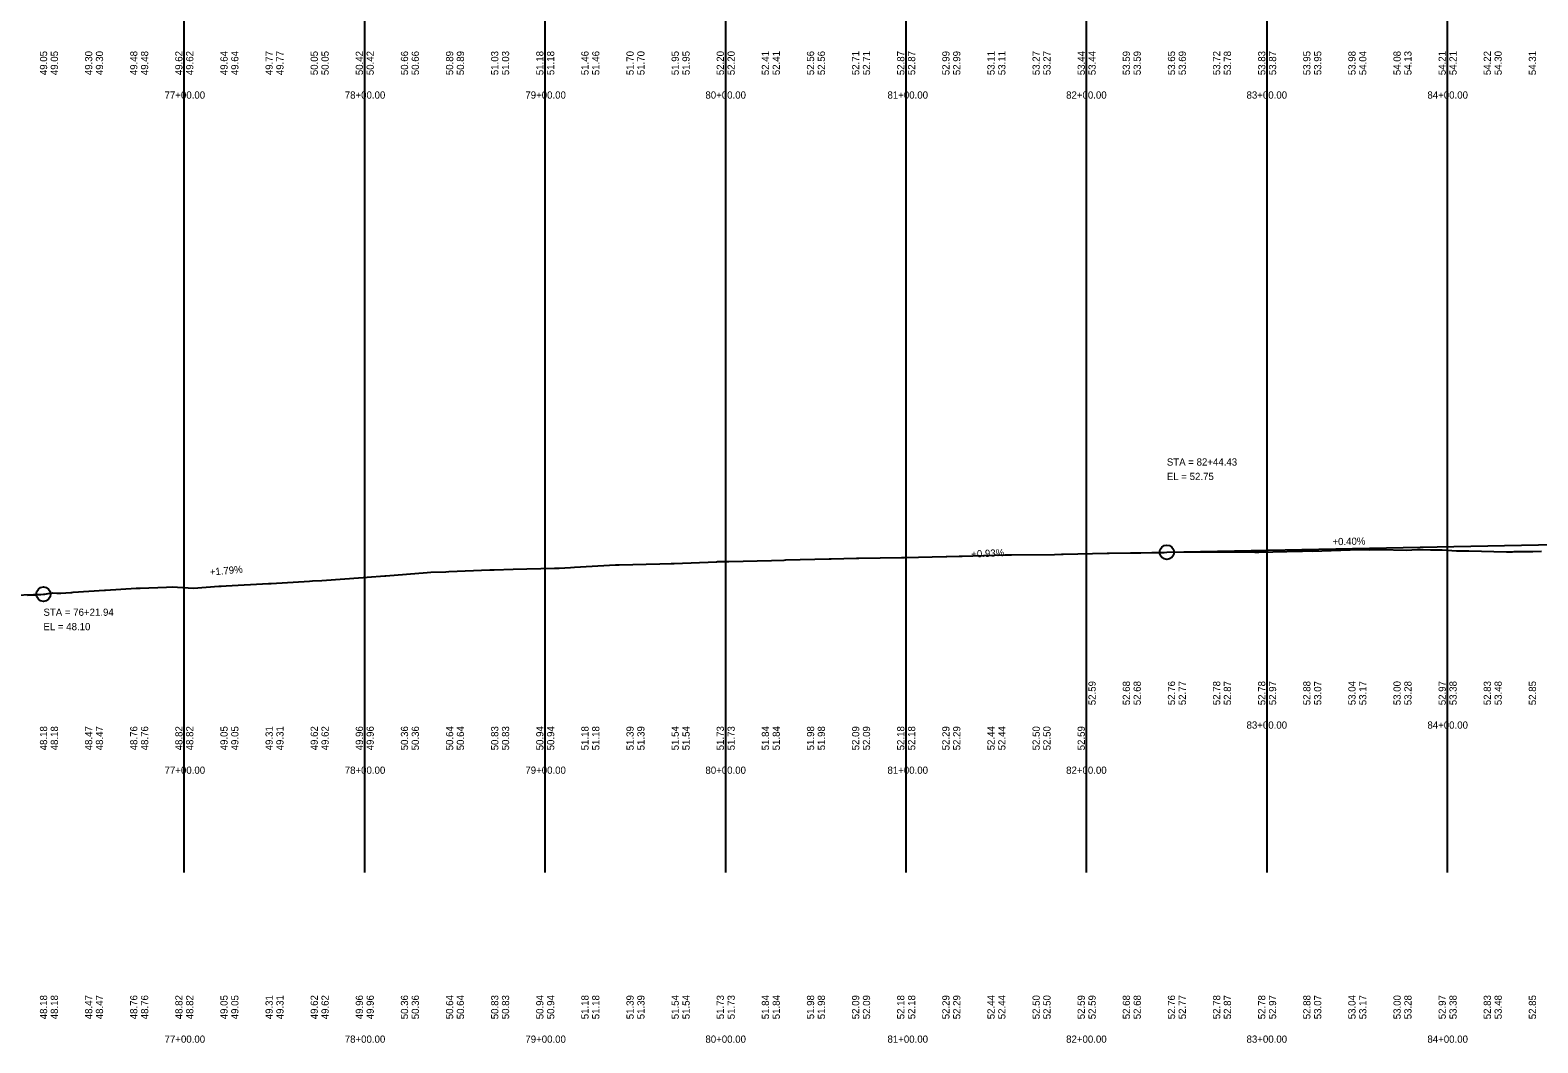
# Model space of a CAD drawing. Extents: x 3880794 to 3915434, y 287517 to 300173.
# Drawn here: x 3906766 to 3907601, y 292382 to 292943 of the extents above; entities that cross this region are included whole.
import ezdxf

# ---------------------------------------------------------------- set-up
doc = ezdxf.new("R2010")
doc.units = 0
for name, color, linetype in [('Level 1', 7, 'Continuous'), ('Level 30', 7, 'Continuous'), ('Level 31', 7, 'Continuous'), ('Level 32', 7, 'Continuous')]:
    doc.layers.add(name, color=color, linetype=linetype)

msp = doc.modelspace()

# ---------------------------------------------------------------- linework, layer by layer
at = {"layer": 'Level 1'}
for p, q in [((3906851.21, 292476.49), (3906851.21, 293504.13)), ((3906951.21, 292476.49), (3906951.21, 293504.13)), ((3907051.21, 292476.49), (3907051.21, 293504.13)), ((3907151.21, 292476.49), (3907151.21, 293504.13)), ((3907251.21, 292476.49), (3907251.21, 293504.13)), ((3907351.21, 292476.49), (3907351.21, 293504.13)), ((3907451.21, 292476.49), (3907451.21, 293504.13)), ((3907551.21, 292476.49), (3907551.21, 293504.13)), ((3907395.64, 292653.84), (3907801.21, 292662.05)), ((3907067.42, 292645.49), (3907090.19, 292646.8)), ((3907090.19, 292646.8), (3907092.19, 292646.83)), ((3907092.19, 292646.83), (3907114.74, 292647.4)), ((3907114.74, 292647.4), (3907121.01, 292647.65)), ((3907121.01, 292647.65), (3907122.73, 292647.69)), ((3907122.73, 292647.69), (3907146.06, 292648.61)), ((3907146.06, 292648.61), (3907146.59, 292648.63)), ((3907146.59, 292648.63), (3907151.39, 292648.74)), ((3907151.39, 292648.74), (3907152.85, 292648.78)), ((3907152.85, 292648.78), (3907176.59, 292649.33)), ((3907176.59, 292649.33), (3907183.63, 292649.52)), ((3907183.63, 292649.52), (3907184.47, 292649.57)), ((3907184.47, 292649.57), (3907208.55, 292650.23)), ((3907208.55, 292650.23), (3907209.61, 292650.26)), ((3907209.61, 292650.26), (3907223.66, 292650.52)), ((3907223.66, 292650.52), (3907224.89, 292650.52)), ((3907224.89, 292650.52), (3907248.61, 292650.95)), ((3907248.61, 292650.95), (3907250.21, 292650.98)), ((3907250.21, 292650.98), (3907273.4, 292651.5)), ((3907273.4, 292651.5), (3907273.78, 292651.5)), ((3907273.78, 292651.5), (3907280.62, 292651.72)), ((3907280.62, 292651.72), (3907282.24, 292651.73)), ((3907282.24, 292651.73), (3907305.82, 292652.46)), ((3907305.82, 292652.46), (3907308.15, 292652.48)), ((3907308.15, 292652.48), (3907309.6, 292652.48)), ((3907309.6, 292652.48), (3907333.33, 292652.65)), ((3907333.33, 292652.65), (3907337.24, 292652.74)), ((3907337.24, 292652.74), (3907338.1, 292652.75)), ((3907338.1, 292652.75), (3907362.58, 292653.3)), ((3907362.58, 292653.3), (3907363.69, 292653.32)), ((3907363.69, 292653.32), (3907381.16, 292653.61)), ((3907381.16, 292653.61), (3907387.37, 292653.71)), ((3907387.37, 292653.71), (3907394.16, 292653.78)), ((3907394.16, 292653.78), (3907395.64, 292653.84)), ((3906899.38, 292636.52), (3906920.66, 292637.82)), ((3906920.66, 292637.82), (3906922.29, 292637.93)), ((3906922.29, 292637.93), (3906927.38, 292638.28)), ((3906927.38, 292638.28), (3906950.25, 292639.84)), ((3906950.25, 292639.84), (3906952.49, 292639.99)), ((3906952.49, 292639.99), (3906962.36, 292640.8)), ((3906962.36, 292640.8), (3906962.95, 292640.84)), ((3906962.95, 292640.84), (3906985.76, 292642.71)), ((3906985.76, 292642.71), (3906987.83, 292642.74)), ((3906987.83, 292642.74), (3906996.2, 292643.05)), ((3906996.2, 292643.05), (3906997.87, 292643.2)), ((3906997.87, 292643.2), (3907020.51, 292644.04)), ((3907020.51, 292644.04), (3907022.96, 292644.16)), ((3907022.96, 292644.16), (3907033.5, 292644.42)), ((3907033.5, 292644.42), (3907056.26, 292644.95)), ((3907056.26, 292644.95), (3907058.49, 292645)), ((3907058.49, 292645), (3907058.95, 292645.01)), ((3907058.95, 292645.01), (3907065.29, 292645.37)), ((3907065.29, 292645.37), (3907067.42, 292645.49)), ((3906751.21, 292629.89), (3906773.16, 292630.63)), ((3906773.16, 292630.63), (3906773.94, 292630.7)), ((3906773.94, 292630.7), (3906775.7, 292630.94)), ((3906775.7, 292630.94), (3906778.36, 292631.31)), ((3906778.36, 292631.31), (3906780.63, 292631.2)), ((3906780.63, 292631.2), (3906781.31, 292631.23)), ((3906781.31, 292631.23), (3906782.49, 292631.2)), ((3906782.49, 292631.2), (3906782.79, 292631.21)), ((3906782.79, 292631.21), (3906788.4, 292631.52)), ((3906788.4, 292631.52), (3906788.85, 292631.58)), ((3906788.85, 292631.58), (3906789.61, 292631.64)), ((3906789.61, 292631.64), (3906806.96, 292632.87)), ((3906806.96, 292632.87), (3906807.59, 292632.81)), ((3906807.59, 292632.81), (3906824.54, 292633.89)), ((3906824.54, 292633.89), (3906826.69, 292633.89)), ((3906826.69, 292633.89), (3906841.38, 292634.5)), ((3906841.38, 292634.5), (3906844.48, 292634.63)), ((3906844.48, 292634.63), (3906856.38, 292633.92)), ((3906856.38, 292633.92), (3906870.32, 292635.04)), ((3906870.32, 292635.04), (3906871.6, 292635.11)), ((3906871.6, 292635.11), (3906874.42, 292635.25)), ((3906874.42, 292635.25), (3906897.89, 292636.48)), ((3906897.89, 292636.48), (3906899.38, 292636.52))]:
    msp.add_line(p, q, dxfattribs=at)
for points in [[(3906826.69, 292633.89), (3906841.38, 292634.5), (3906844.48, 292634.63), (3906856.38, 292633.92), (3906870.32, 292635.04), (3906871.6, 292635.11), (3906874.42, 292635.25), (3906897.89, 292636.48), (3906899.38, 292636.52), (3906920.66, 292637.82), (3906922.29, 292637.93), (3906927.38, 292638.28), (3906950.25, 292639.84), (3906952.49, 292639.99), (3906962.36, 292640.8), (3906962.95, 292640.84), (3906985.76, 292642.71), (3906987.83, 292642.74), (3906996.2, 292643.05), (3906997.87, 292643.2), (3907020.51, 292644.04), (3907022.96, 292644.16), (3907033.5, 292644.42), (3907056.26, 292644.95), (3907058.49, 292645), (3907058.95, 292645.01), (3907065.29, 292645.37), (3907067.42, 292645.49), (3907090.19, 292646.8), (3907092.19, 292646.83), (3907114.74, 292647.4), (3907121.01, 292647.65), (3907122.73, 292647.69), (3907146.06, 292648.61), (3907146.59, 292648.63), (3907151.39, 292648.74), (3907152.85, 292648.78), (3907176.59, 292649.33), (3907183.63, 292649.52), (3907184.47, 292649.57), (3907208.55, 292650.23), (3907209.61, 292650.26), (3907223.66, 292650.52), (3907224.89, 292650.52), (3907248.61, 292650.95), (3907250.21, 292650.98), (3907273.4, 292651.5), (3907273.78, 292651.5), (3907280.62, 292651.72), (3907282.24, 292651.73), (3907305.82, 292652.46), (3907308.15, 292652.48), (3907309.6, 292652.48), (3907333.33, 292652.65), (3907337.24, 292652.74), (3907338.1, 292652.75), (3907362.58, 292653.3), (3907363.69, 292653.32), (3907387.37, 292653.71), (3907394.16, 292653.78), (3907395.64, 292653.84), (3907419.16, 292654.07), (3907420.61, 292654.06), (3907444.32, 292653.87), (3907444.91, 292653.93), (3907445.77, 292653.95), (3907446.65, 292653.93), (3907469.81, 292654.43), (3907470.79, 292654.45), (3907473.08, 292654.54), (3907474.38, 292654.54), (3907476.27, 292654.5), (3907497.22, 292655.22), (3907500.5, 292655.31), (3907507.88, 292655.18), (3907514.07, 292655.29), (3907528.22, 292655.07), (3907534.61, 292655.4), (3907536.39, 292655.33), (3907537.62, 292655.35), (3907541.66, 292655.2), (3907545.06, 292655.12), (3907548.27, 292655.11), (3907556.2, 292654.71), (3907560.34, 292654.64), (3907563.01, 292654.57), (3907583.86, 292654.07), (3907587.12, 292654.02), (3907588.09, 292654.34), (3907591.56, 292654.3), (3907598.36, 292654.31), (3907603.21, 292654.42)], [(3906764.32, 292629.98), (3906768.41, 292630.17), (3906769.43, 292630.29), (3906773.94, 292630.7), (3906775.7, 292630.94), (3906778.36, 292631.31), (3906780.63, 292631.2), (3906781.31, 292631.23), (3906782.49, 292631.2), (3906782.79, 292631.21), (3906788.4, 292631.52), (3906788.85, 292631.58), (3906789.61, 292631.64), (3906806.96, 292632.87), (3906807.59, 292632.81), (3906824.54, 292633.89), (3906826.69, 292633.89)]]:
    msp.add_lwpolyline(points, dxfattribs=at)
for centre in [(3907395.64, 292653.84), (3906773.16, 292630.63)]:
    msp.add_circle(centre, 4, dxfattribs=at)

# ---------------------------------------------------------------- texts
at = {"layer": 'Level 30'}
for s, p in [('77+00.00', (3906840.29, 292905.16)), ('77+00.00', (3906840.29, 292905.16)), ('78+00.00', (3906940.13, 292905.16)), ('78+00.00', (3906940.13, 292905.16)), ('79+00.00', (3907040.19, 292905.16)), ('79+00.00', (3907040.19, 292905.16)), ('80+00.00', (3907139.97, 292905.16)), ('80+00.00', (3907139.97, 292905.16)), ('81+00.00', (3907240.85, 292905.16)), ('81+00.00', (3907240.85, 292905.16)), ('82+00.00', (3907339.84, 292905.16)), ('82+00.00', (3907339.84, 292905.16)), ('83+00.00', (3907439.81, 292905.16)), ('83+00.00', (3907439.81, 292905.16)), ('84+00.00', (3907540.03, 292905.16)), ('84+00.00', (3907540.03, 292905.16)), ('83+00.00', (3907439.81, 292556.11)), ('83+00.00', (3907439.81, 292556.11)), ('84+00.00', (3907540.03, 292556.11)), ('84+00.00', (3907540.03, 292556.11)), ('77+00.00', (3906840.29, 292531.11)), ('77+00.00', (3906840.29, 292531.11)), ('78+00.00', (3906940.13, 292531.11)), ('78+00.00', (3906940.13, 292531.11)), ('79+00.00', (3907040.19, 292531.11)), ('79+00.00', (3907040.19, 292531.11)), ('80+00.00', (3907139.97, 292531.11)), ('80+00.00', (3907139.97, 292531.11)), ('81+00.00', (3907240.85, 292531.11)), ('81+00.00', (3907240.85, 292531.11)), ('82+00.00', (3907339.84, 292531.11)), ('82+00.00', (3907339.84, 292531.11)), ('77+00.00', (3906840.29, 292382.11)), ('77+00.00', (3906840.29, 292382.11)), ('78+00.00', (3906940.13, 292382.11)), ('78+00.00', (3906940.13, 292382.11)), ('79+00.00', (3907040.19, 292382.11)), ('79+00.00', (3907040.19, 292382.11)), ('80+00.00', (3907139.97, 292382.11)), ('80+00.00', (3907139.97, 292382.11)), ('81+00.00', (3907240.85, 292382.11)), ('81+00.00', (3907240.85, 292382.11)), ('82+00.00', (3907339.84, 292382.11)), ('82+00.00', (3907339.84, 292382.11)), ('83+00.00', (3907439.81, 292382.11)), ('83+00.00', (3907439.81, 292382.11)), ('84+00.00', (3907540.03, 292382.11)), ('84+00.00', (3907540.03, 292382.11))]:
    msp.add_text(s, height=4, dxfattribs=at).set_placement(p)
at = {"layer": 'Level 31'}
for s, p in [('STA = 82+44.43', (3907395.64, 292701.85)), ('EL = 52.75', (3907395.64, 292693.85)), ('STA = 76+21.94', (3906773.16, 292618.63)), ('EL = 48.10', (3906773.16, 292610.63))]:
    msp.add_text(s, height=4, dxfattribs=at).set_placement(p)
for s, rotation, p in [('+0.93%', 2.66002, (3907287.35, 292650.82)), ('+0.40%', 1.15914, (3907487.42, 292657.7)), ('+1.79%', 5.11098, (3906865.49, 292640.9)), ('52.59', 90, (3907356.21, 292569.11)), ('52.68', 90, (3907375.21, 292569.11)), ('52.68', 90, (3907381.21, 292569.11)), ('52.76', 90, (3907400.21, 292569.11)), ('52.77', 90, (3907406.21, 292569.11)), ('52.78', 90, (3907425.21, 292569.11)), ('52.87', 90, (3907431.21, 292569.11)), ('52.78', 90, (3907450.21, 292569.11)), ('52.97', 90, (3907456.21, 292569.11)), ('52.88', 90, (3907475.21, 292569.11)), ('53.07', 90, (3907481.21, 292569.11)), ('53.04', 90, (3907500.21, 292569.11)), ('53.17', 90, (3907506.21, 292569.11)), ('53.00', 90, (3907525.21, 292569.11)), ('53.28', 90, (3907531.21, 292569.11)), ('52.97', 90, (3907550.21, 292569.11)), ('53.38', 90, (3907556.21, 292569.11)), ('52.83', 90, (3907575.21, 292569.11)), ('53.48', 90, (3907581.21, 292569.11)), ('52.85', 90, (3907600.21, 292569.11)), ('48.18', 90, (3906775.21, 292544.11)), ('48.18', 90, (3906781.21, 292544.11)), ('48.47', 90, (3906800.21, 292544.11)), ('48.47', 90, (3906806.21, 292544.11)), ('48.76', 90, (3906825.21, 292544.11)), ('48.76', 90, (3906831.21, 292544.11)), ('48.82', 90, (3906850.21, 292544.11)), ('48.82', 90, (3906856.21, 292544.11)), ('49.05', 90, (3906875.21, 292544.11)), ('49.05', 90, (3906881.21, 292544.11)), ('49.31', 90, (3906900.21, 292544.11)), ('49.31', 90, (3906906.21, 292544.11)), ('49.62', 90, (3906925.21, 292544.11)), ('49.62', 90, (3906931.21, 292544.11)), ('49.96', 90, (3906950.21, 292544.11)), ('49.96', 90, (3906956.21, 292544.11)), ('50.36', 90, (3906975.21, 292544.11)), ('50.36', 90, (3906981.21, 292544.11)), ('50.64', 90, (3907000.21, 292544.11)), ('50.64', 90, (3907006.21, 292544.11)), ('50.83', 90, (3907025.21, 292544.11)), ('50.83', 90, (3907031.21, 292544.11)), ('50.94', 90, (3907050.21, 292544.11)), ('50.94', 90, (3907056.21, 292544.11)), ('51.18', 90, (3907075.21, 292544.11)), ('51.18', 90, (3907081.21, 292544.11)), ('51.39', 90, (3907100.21, 292544.11)), ('51.39', 90, (3907106.21, 292544.11)), ('51.54', 90, (3907125.21, 292544.11)), ('51.54', 90, (3907131.21, 292544.11)), ('51.73', 90, (3907150.21, 292544.11)), ('51.73', 90, (3907156.21, 292544.11)), ('51.84', 90, (3907175.21, 292544.11)), ('51.84', 90, (3907181.21, 292544.11)), ('51.98', 90, (3907200.21, 292544.11)), ('51.98', 90, (3907206.21, 292544.11)), ('52.09', 90, (3907225.21, 292544.11)), ('52.09', 90, (3907231.21, 292544.11)), ('52.18', 90, (3907250.21, 292544.11)), ('52.18', 90, (3907256.21, 292544.11)), ('52.29', 90, (3907275.21, 292544.11)), ('52.29', 90, (3907281.21, 292544.11)), ('52.44', 90, (3907300.21, 292544.11)), ('52.44', 90, (3907306.21, 292544.11)), ('52.50', 90, (3907325.21, 292544.11)), ('52.50', 90, (3907331.21, 292544.11)), ('52.59', 90, (3907350.21, 292544.11)), ('48.18', 90, (3906775.21, 292395.11)), ('48.18', 90, (3906781.21, 292395.11)), ('48.47', 90, (3906800.21, 292395.11)), ('48.47', 90, (3906806.21, 292395.11)), ('48.76', 90, (3906825.21, 292395.11)), ('48.76', 90, (3906831.21, 292395.11)), ('48.82', 90, (3906850.21, 292395.11)), ('48.82', 90, (3906856.21, 292395.11)), ('49.05', 90, (3906875.21, 292395.11)), ('49.05', 90, (3906881.21, 292395.11)), ('49.31', 90, (3906900.21, 292395.11)), ('49.31', 90, (3906906.21, 292395.11)), ('49.62', 90, (3906925.21, 292395.11)), ('49.62', 90, (3906931.21, 292395.11)), ('49.96', 90, (3906950.21, 292395.11)), ('49.96', 90, (3906956.21, 292395.11)), ('50.36', 90, (3906975.21, 292395.11)), ('50.36', 90, (3906981.21, 292395.11)), ('50.64', 90, (3907000.21, 292395.11)), ('50.64', 90, (3907006.21, 292395.11)), ('50.83', 90, (3907025.21, 292395.11)), ('50.83', 90, (3907031.21, 292395.11)), ('50.94', 90, (3907050.21, 292395.11)), ('50.94', 90, (3907056.21, 292395.11)), ('51.18', 90, (3907075.21, 292395.11)), ('51.18', 90, (3907081.21, 292395.11)), ('51.39', 90, (3907100.21, 292395.11)), ('51.39', 90, (3907106.21, 292395.11)), ('51.54', 90, (3907125.21, 292395.11)), ('51.54', 90, (3907131.21, 292395.11)), ('51.73', 90, (3907150.21, 292395.11)), ('51.73', 90, (3907156.21, 292395.11)), ('51.84', 90, (3907175.21, 292395.11)), ('51.84', 90, (3907181.21, 292395.11)), ('51.98', 90, (3907200.21, 292395.11)), ('51.98', 90, (3907206.21, 292395.11)), ('52.09', 90, (3907225.21, 292395.11)), ('52.09', 90, (3907231.21, 292395.11)), ('52.18', 90, (3907250.21, 292395.11)), ('52.18', 90, (3907256.21, 292395.11)), ('52.29', 90, (3907275.21, 292395.11)), ('52.29', 90, (3907281.21, 292395.11)), ('52.44', 90, (3907300.21, 292395.11)), ('52.44', 90, (3907306.21, 292395.11)), ('52.50', 90, (3907325.21, 292395.11)), ('52.50', 90, (3907331.21, 292395.11)), ('52.59', 90, (3907350.21, 292395.11)), ('52.59', 90, (3907356.21, 292395.11)), ('52.68', 90, (3907375.21, 292395.11)), ('52.68', 90, (3907381.21, 292395.11)), ('52.76', 90, (3907400.21, 292395.11)), ('52.77', 90, (3907406.21, 292395.11)), ('52.78', 90, (3907425.21, 292395.11)), ('52.87', 90, (3907431.21, 292395.11)), ('52.78', 90, (3907450.21, 292395.11)), ('52.97', 90, (3907456.21, 292395.11)), ('52.88', 90, (3907475.21, 292395.11)), ('53.07', 90, (3907481.21, 292395.11)), ('53.04', 90, (3907500.21, 292395.11)), ('53.17', 90, (3907506.21, 292395.11)), ('53.00', 90, (3907525.21, 292395.11)), ('53.28', 90, (3907531.21, 292395.11)), ('52.97', 90, (3907550.21, 292395.11)), ('53.38', 90, (3907556.21, 292395.11)), ('52.83', 90, (3907575.21, 292395.11)), ('53.48', 90, (3907581.21, 292395.11)), ('52.85', 90, (3907600.21, 292395.11))]:
    msp.add_text(s, height=4, rotation=rotation, dxfattribs=at).set_placement(p)
at = {"layer": 'Level 32'}
for s, p in [('49.05', (3906775.21, 292918.16)), ('49.05', (3906781.21, 292918.16)), ('49.30', (3906800.21, 292918.16)), ('49.30', (3906806.21, 292918.16)), ('49.48', (3906825.21, 292918.16)), ('49.48', (3906831.21, 292918.16)), ('49.62', (3906850.21, 292918.16)), ('49.62', (3906856.21, 292918.16)), ('49.64', (3906875.21, 292918.16)), ('49.64', (3906881.21, 292918.16)), ('49.77', (3906900.21, 292918.16)), ('49.77', (3906906.21, 292918.16)), ('50.05', (3906925.21, 292918.16)), ('50.05', (3906931.21, 292918.16)), ('50.42', (3906950.21, 292918.16)), ('50.42', (3906956.21, 292918.16)), ('50.66', (3906975.21, 292918.16)), ('50.66', (3906981.21, 292918.16)), ('50.89', (3907000.21, 292918.16)), ('50.89', (3907006.21, 292918.16)), ('51.03', (3907025.21, 292918.16)), ('51.03', (3907031.21, 292918.16)), ('51.18', (3907050.21, 292918.16)), ('51.18', (3907056.21, 292918.16)), ('51.46', (3907075.21, 292918.16)), ('51.46', (3907081.21, 292918.16)), ('51.70', (3907100.21, 292918.16)), ('51.70', (3907106.21, 292918.16)), ('51.95', (3907125.21, 292918.16)), ('51.95', (3907131.21, 292918.16)), ('52.20', (3907150.21, 292918.16)), ('52.20', (3907156.21, 292918.16)), ('52.41', (3907175.21, 292918.16)), ('52.41', (3907181.21, 292918.16)), ('52.56', (3907200.21, 292918.16)), ('52.56', (3907206.21, 292918.16)), ('52.71', (3907225.21, 292918.16)), ('52.71', (3907231.21, 292918.16)), ('52.87', (3907250.21, 292918.16)), ('52.87', (3907256.21, 292918.16)), ('52.99', (3907275.21, 292918.16)), ('52.99', (3907281.21, 292918.16)), ('53.11', (3907300.21, 292918.16)), ('53.11', (3907306.21, 292918.16)), ('53.27', (3907325.21, 292918.16)), ('53.27', (3907331.21, 292918.16)), ('53.44', (3907350.21, 292918.16)), ('53.44', (3907356.21, 292918.16)), ('53.59', (3907375.21, 292918.16)), ('53.59', (3907381.21, 292918.16)), ('53.65', (3907400.21, 292918.16)), ('53.69', (3907406.21, 292918.16)), ('53.72', (3907425.21, 292918.16)), ('53.78', (3907431.21, 292918.16)), ('53.83', (3907450.21, 292918.16)), ('53.87', (3907456.21, 292918.16)), ('53.95', (3907475.21, 292918.16)), ('53.95', (3907481.21, 292918.16)), ('53.98', (3907500.21, 292918.16)), ('54.04', (3907506.21, 292918.16)), ('54.08', (3907525.21, 292918.16)), ('54.13', (3907531.21, 292918.16)), ('54.21', (3907550.21, 292918.16)), ('54.21', (3907556.21, 292918.16)), ('54.22', (3907575.21, 292918.16)), ('54.30', (3907581.21, 292918.16)), ('54.31', (3907600.21, 292918.16))]:
    msp.add_text(s, height=4, rotation=90, dxfattribs=at).set_placement(p)

doc.saveas('drawing.dxf')
